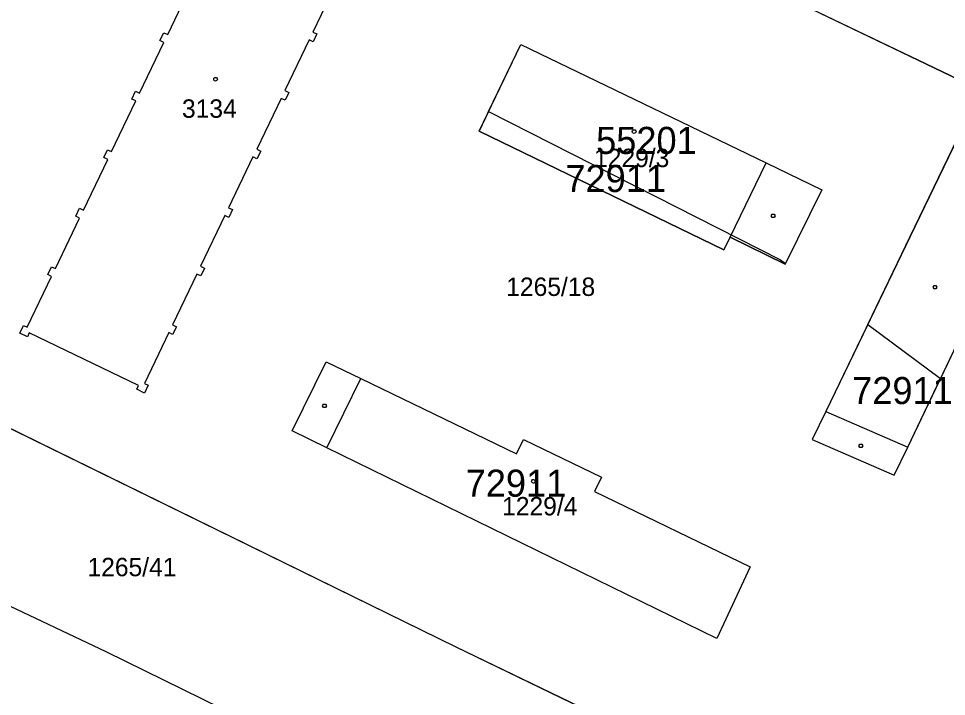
# Model space of a CAD drawing. Extents: x -779618 to -776429, y -1144546 to -1143350.
# Drawn here: x -777222.5 to -777136.8, y -1143980.2 to -1143917.5 of the extents above; entities that cross this region are included whole.
import ezdxf

# ---------------------------------------------------------------- set-up
doc = ezdxf.new("R2010")
doc.units = 0
for name, color, linetype in [('1', 7, 'Continuous'), ('11', 7, 'Continuous'), ('12', 7, 'Continuous'), ('2', 7, 'Continuous'), ('4', 7, 'Continuous'), ('5', 7, 'Continuous')]:
    doc.layers.add(name, color=color, linetype=linetype)

msp = doc.modelspace()

# ---------------------------------------------------------------- linework, layer by layer
at = {"layer": '1'}
for p, q in [((-777133.63, -1143924.16), (-777157.17, -1143912.85)), ((-777208.73, -1143919.02), (-777206.49, -1143914.33)), ((-777193.07, -1143914.09), (-777195.31, -1143918.78)), ((-777209.44, -1143919.56), (-777209.09, -1143918.84)), ((-777209.09, -1143918.84), (-777208.73, -1143919.02)), ((-777195.31, -1143918.78), (-777194.95, -1143918.95)), ((-777194.95, -1143918.95), (-777195.3, -1143919.68)), ((-777211.33, -1143924.42), (-777209.08, -1143919.74)), ((-777209.08, -1143919.74), (-777209.44, -1143919.56)), ((-777195.66, -1143919.5), (-777197.91, -1143924.19)), ((-777195.3, -1143919.68), (-777195.66, -1143919.5)), ((-777179.97, -1143927.94), (-777176.1, -1143919.92)), ((-777176.1, -1143919.92), (-777153.45, -1143930.87)), ((-777212.03, -1143924.97), (-777211.69, -1143924.25)), ((-777211.69, -1143924.25), (-777211.33, -1143924.42)), ((-777197.91, -1143924.19), (-777197.55, -1143924.36)), ((-777133.63, -1143924.16), (-777140.15, -1143937.67)), ((-777213.92, -1143929.83), (-777211.67, -1143925.14)), ((-777211.67, -1143925.14), (-777212.03, -1143924.97)), ((-777198.25, -1143924.91), (-777200.5, -1143929.6)), ((-777197.89, -1143925.08), (-777198.25, -1143924.91)), ((-777197.55, -1143924.36), (-777197.89, -1143925.08)), ((-777157.35, -1143938.91), (-777179.97, -1143927.94)), ((-777214.62, -1143930.38), (-777214.28, -1143929.66)), ((-777214.28, -1143929.66), (-777213.92, -1143929.83)), ((-777200.85, -1143930.32), (-777203.1, -1143935.01)), ((-777200.49, -1143930.49), (-777200.85, -1143930.32)), ((-777200.5, -1143929.6), (-777200.14, -1143929.77)), ((-777200.14, -1143929.77), (-777200.49, -1143930.49)), ((-777216.51, -1143935.24), (-777214.26, -1143930.55)), ((-777214.26, -1143930.55), (-777214.62, -1143930.38)), ((-777153.45, -1143930.87), (-777148.31, -1143933.36)), ((-777148.31, -1143933.36), (-777151.69, -1143940.24)), ((-777217.22, -1143935.78), (-777216.87, -1143935.06)), ((-777216.87, -1143935.06), (-777216.51, -1143935.24)), ((-777203.1, -1143935.01), (-777202.74, -1143935.18)), ((-777202.74, -1143935.18), (-777203.08, -1143935.9)), ((-777219.1, -1143940.64), (-777216.86, -1143935.96)), ((-777216.86, -1143935.96), (-777217.22, -1143935.78)), ((-777203.44, -1143935.73), (-777205.69, -1143940.42)), ((-777203.08, -1143935.9), (-777203.44, -1143935.73)), ((-777156.78, -1143937.74), (-777157.35, -1143938.91)), ((-777151.69, -1143940.24), (-777156.78, -1143937.74)), ((-777140.15, -1143937.67), (-777147.94, -1143953.83)), ((-777219.81, -1143941.19), (-777219.46, -1143940.47)), ((-777219.46, -1143940.47), (-777219.1, -1143940.64)), ((-777205.69, -1143940.42), (-777205.33, -1143940.59)), ((-777205.33, -1143940.59), (-777205.68, -1143941.31)), ((-777221.7, -1143946.05), (-777219.45, -1143941.36)), ((-777219.45, -1143941.36), (-777219.81, -1143941.19)), ((-777206.04, -1143941.14), (-777208.29, -1143945.83)), ((-777205.68, -1143941.31), (-777206.04, -1143941.14)), ((-777140.36, -1143957.12), (-777132.6, -1143940.84)), ((-777222.4, -1143946.6), (-777222.06, -1143945.88)), ((-777221.68, -1143946.94), (-777222.4, -1143946.6)), ((-777222.06, -1143945.88), (-777221.7, -1143946.05)), ((-777221.51, -1143946.58), (-777221.68, -1143946.94)), ((-777211.42, -1143951.42), (-777221.51, -1143946.58)), ((-777208.63, -1143946.55), (-777210.88, -1143951.24)), ((-777208.27, -1143946.72), (-777208.63, -1143946.55)), ((-777208.29, -1143945.83), (-777207.93, -1143946)), ((-777207.93, -1143946), (-777208.27, -1143946.72)), ((-777197.24, -1143955.62), (-777194.08, -1143949.25)), ((-777194.08, -1143949.25), (-777190.89, -1143950.8)), ((-777233.61, -1143950.34), (-777182.11, -1143975.59)), ((-777190.89, -1143950.8), (-777176.5, -1143957.76)), ((-777211.59, -1143951.78), (-777211.42, -1143951.42)), ((-777210.88, -1143951.24), (-777210.52, -1143951.41)), ((-777210.52, -1143951.41), (-777210.87, -1143952.13)), ((-777210.87, -1143952.13), (-777211.59, -1143951.78)), ((-777263.88, -1143952.69), (-777214.44, -1143976.01)), ((-777147.94, -1143953.83), (-777149.2, -1143956.43)), ((-777194.04, -1143957.18), (-777197.24, -1143955.62)), ((-777176.5, -1143957.76), (-777175.86, -1143956.43)), ((-777175.86, -1143956.43), (-777168.67, -1143959.91)), ((-777149.2, -1143956.43), (-777141.61, -1143959.73)), ((-777157.99, -1143974.82), (-777194.04, -1143957.18)), ((-777141.61, -1143959.73), (-777140.36, -1143957.12)), ((-777168.67, -1143959.91), (-777169.31, -1143961.24)), ((-777169.31, -1143961.24), (-777154.93, -1143968.2)), ((-777154.93, -1143968.2), (-777157.99, -1143974.82)), ((-777182.11, -1143975.59), (-777151.49, -1143990.35)), ((-777214.44, -1143976.01), (-777171.18, -1143997.24))]:
    msp.add_line(p, q, dxfattribs=at)
at = {"layer": '11'}
msp.add_line((-777144.07, -1143945.8), (-777137.35, -1143950.8), dxfattribs=at)
for points in [[(-777144.07, -1143945.8), (-777140.15, -1143937.67), (-777133.63, -1143924.16), (-777157.17, -1143912.85), (-777169.76, -1143906.8), (-777164.83, -1143896.6), (-777152.28, -1143902.66), (-777127.18, -1143914.79), (-777125.66, -1143911.89), (-777123.69, -1143912.92), (-777122.34, -1143910.06), (-777116.5, -1143912.8), (-777119.25, -1143918.66), (-777099.16, -1143928.16), (-777100.35, -1143930.67), (-777097.85, -1143931.84), (-777100.33, -1143937.03), (-777102.79, -1143935.87), (-777103.98, -1143938.41), (-777126.31, -1143927.68), (-777132.6, -1143940.84), (-777137.35, -1143950.8)], [(-777179.09, -1143926.12), (-777176.1, -1143919.92), (-777153.45, -1143930.87), (-777148.31, -1143933.36), (-777151.65, -1143940.15)], [(-777179.09, -1143926.12), (-777179.97, -1143927.94), (-777157.35, -1143938.91), (-777156.78, -1143937.74), (-777151.69, -1143940.24), (-777151.65, -1143940.15)], [(-777179.09, -1143926.12), (-777152.11, -1143939.81), (-777151.65, -1143940.15)], [(-777144.07, -1143945.8), (-777147.94, -1143953.83), (-777149.2, -1143956.43), (-777141.61, -1143959.73), (-777140.36, -1143957.12), (-777137.35, -1143950.8)], [(-777233.61, -1143950.34), (-777182.11, -1143975.59), (-777151.49, -1143990.35), (-777149.1, -1143989.23), (-777148.68, -1143990.13), (-777144.83, -1143988.32), (-777141.63, -1143995.11), (-777128.13, -1144001.62), (-777129.93, -1143997.79), (-777127.9, -1143996.84), (-777129.57, -1143993.28), (-777118.21, -1143987.96), (-777116.54, -1143991.53), (-777114.5, -1143990.57), (-777103.79, -1144013.4), (-777099.68, -1144015.4), (-777097.63, -1144016.39), (-777109.29, -1143991.28), (-777109.82, -1143985.95), (-777106.25, -1143978.69)]]:
    msp.add_lwpolyline(points, dxfattribs=at)
msp.add_lwpolyline([(-777194.08, -1143949.25), (-777190.89, -1143950.8), (-777176.5, -1143957.76), (-777175.86, -1143956.43), (-777168.67, -1143959.91), (-777169.31, -1143961.24), (-777154.93, -1143968.2), (-777157.99, -1143974.82), (-777194.04, -1143957.18), (-777197.24, -1143955.62)], close=True, dxfattribs=at)
at = {"layer": '12'}
for p, q in [((-777133.63, -1143924.16), (-777157.17, -1143912.85)), ((-777208.73, -1143919.02), (-777206.49, -1143914.33)), ((-777193.07, -1143914.09), (-777195.31, -1143918.78)), ((-777209.44, -1143919.56), (-777209.09, -1143918.84)), ((-777209.09, -1143918.84), (-777208.73, -1143919.02)), ((-777195.31, -1143918.78), (-777194.95, -1143918.95)), ((-777194.95, -1143918.95), (-777195.3, -1143919.68)), ((-777211.33, -1143924.42), (-777209.08, -1143919.74)), ((-777209.08, -1143919.74), (-777209.44, -1143919.56)), ((-777195.66, -1143919.5), (-777197.91, -1143924.19)), ((-777195.3, -1143919.68), (-777195.66, -1143919.5)), ((-777179.97, -1143927.94), (-777176.1, -1143919.92)), ((-777176.1, -1143919.92), (-777153.45, -1143930.87)), ((-777212.03, -1143924.97), (-777211.69, -1143924.25)), ((-777211.69, -1143924.25), (-777211.33, -1143924.42)), ((-777197.91, -1143924.19), (-777197.55, -1143924.36)), ((-777213.92, -1143929.83), (-777211.67, -1143925.14)), ((-777211.67, -1143925.14), (-777212.03, -1143924.97)), ((-777198.25, -1143924.91), (-777200.5, -1143929.6)), ((-777197.89, -1143925.08), (-777198.25, -1143924.91)), ((-777197.55, -1143924.36), (-777197.89, -1143925.08)), ((-777157.35, -1143938.91), (-777179.97, -1143927.94)), ((-777214.62, -1143930.38), (-777214.28, -1143929.66)), ((-777214.28, -1143929.66), (-777213.92, -1143929.83)), ((-777200.85, -1143930.32), (-777203.1, -1143935.01)), ((-777200.49, -1143930.49), (-777200.85, -1143930.32)), ((-777200.5, -1143929.6), (-777200.14, -1143929.77)), ((-777200.14, -1143929.77), (-777200.49, -1143930.49)), ((-777216.51, -1143935.24), (-777214.26, -1143930.55)), ((-777214.26, -1143930.55), (-777214.62, -1143930.38)), ((-777156.78, -1143937.74), (-777153.45, -1143930.87)), ((-777217.22, -1143935.78), (-777216.87, -1143935.06)), ((-777216.87, -1143935.06), (-777216.51, -1143935.24)), ((-777203.1, -1143935.01), (-777202.74, -1143935.18)), ((-777202.74, -1143935.18), (-777203.08, -1143935.9)), ((-777219.1, -1143940.64), (-777216.86, -1143935.96)), ((-777216.86, -1143935.96), (-777217.22, -1143935.78)), ((-777203.44, -1143935.73), (-777205.69, -1143940.42)), ((-777203.08, -1143935.9), (-777203.44, -1143935.73)), ((-777156.78, -1143937.74), (-777157.35, -1143938.91)), ((-777219.81, -1143941.19), (-777219.46, -1143940.47)), ((-777219.46, -1143940.47), (-777219.1, -1143940.64)), ((-777205.69, -1143940.42), (-777205.33, -1143940.59)), ((-777205.33, -1143940.59), (-777205.68, -1143941.31)), ((-777221.7, -1143946.05), (-777219.45, -1143941.36)), ((-777219.45, -1143941.36), (-777219.81, -1143941.19)), ((-777206.04, -1143941.14), (-777208.29, -1143945.83)), ((-777205.68, -1143941.31), (-777206.04, -1143941.14)), ((-777222.4, -1143946.6), (-777222.06, -1143945.88)), ((-777221.68, -1143946.94), (-777222.4, -1143946.6)), ((-777222.06, -1143945.88), (-777221.7, -1143946.05)), ((-777221.51, -1143946.58), (-777221.68, -1143946.94)), ((-777211.42, -1143951.42), (-777221.51, -1143946.58)), ((-777208.63, -1143946.55), (-777210.88, -1143951.24)), ((-777208.27, -1143946.72), (-777208.63, -1143946.55)), ((-777208.29, -1143945.83), (-777207.93, -1143946)), ((-777207.93, -1143946), (-777208.27, -1143946.72)), ((-777194.04, -1143957.18), (-777190.89, -1143950.8)), ((-777190.89, -1143950.8), (-777176.5, -1143957.76)), ((-777211.59, -1143951.78), (-777211.42, -1143951.42)), ((-777210.88, -1143951.24), (-777210.52, -1143951.41)), ((-777210.52, -1143951.41), (-777210.87, -1143952.13)), ((-777210.87, -1143952.13), (-777211.59, -1143951.78)), ((-777176.5, -1143957.76), (-777175.86, -1143956.43)), ((-777175.86, -1143956.43), (-777168.67, -1143959.91)), ((-777157.99, -1143974.82), (-777194.04, -1143957.18)), ((-777168.67, -1143959.91), (-777169.31, -1143961.24)), ((-777169.31, -1143961.24), (-777154.93, -1143968.2)), ((-777154.93, -1143968.2), (-777157.99, -1143974.82))]:
    msp.add_line(p, q, dxfattribs=at)
at = {"layer": '4'}
for p, q in [((-777156.78, -1143937.74), (-777153.45, -1143930.87)), ((-777194.04, -1143957.18), (-777190.89, -1143950.8)), ((-777147.94, -1143953.83), (-777140.36, -1143957.12))]:
    msp.add_line(p, q, dxfattribs=at)
at = {"layer": '5'}
for points in [[(-777204.31, -1143922.97), (-777204.21, -1143922.99), (-777204.16, -1143923.08), (-777204.14, -1143923.14), (-777204.16, -1143923.23), (-777204.24, -1143923.3), (-777204.31, -1143923.31), (-777204.4, -1143923.28), (-777204.46, -1143923.22), (-777204.48, -1143923.14), (-777204.46, -1143923.05), (-777204.38, -1143922.98)], [(-777165.64, -1143927.8), (-777165.54, -1143927.82), (-777165.49, -1143927.91), (-777165.47, -1143927.97), (-777165.49, -1143928.06), (-777165.57, -1143928.13), (-777165.64, -1143928.14), (-777165.73, -1143928.11), (-777165.79, -1143928.05), (-777165.81, -1143927.97), (-777165.79, -1143927.88), (-777165.71, -1143927.81)], [(-777152.72, -1143935.61), (-777152.63, -1143935.76), (-777152.72, -1143935.91), (-777152.9, -1143935.91), (-777152.99, -1143935.76), (-777152.9, -1143935.61)], [(-777137.76, -1143942.2), (-777137.67, -1143942.35), (-777137.76, -1143942.5), (-777137.94, -1143942.5), (-777138.03, -1143942.35), (-777137.94, -1143942.2)], [(-777194.16, -1143953.16), (-777194.07, -1143953.31), (-777194.16, -1143953.46), (-777194.34, -1143953.46), (-777194.43, -1143953.31), (-777194.34, -1143953.16)], [(-777144.61, -1143956.85), (-777144.52, -1143957), (-777144.61, -1143957.15), (-777144.79, -1143957.15), (-777144.88, -1143957), (-777144.79, -1143956.85)], [(-777174.95, -1143960.12), (-777174.85, -1143960.14), (-777174.8, -1143960.23), (-777174.78, -1143960.29), (-777174.8, -1143960.38), (-777174.88, -1143960.45), (-777174.95, -1143960.46), (-777175.04, -1143960.43), (-777175.1, -1143960.37), (-777175.12, -1143960.29), (-777175.1, -1143960.2), (-777175.02, -1143960.13)]]:
    msp.add_lwpolyline(points, close=True, dxfattribs=at)

# ---------------------------------------------------------------- texts
at = {"layer": '11'}
for s, p in [('55201', (-777169.155, -1143930.04)), ('72911', (-777171.995, -1143933.56)), ('72911', (-777145.505, -1143953.15)), ('72911', (-777181.205, -1143961.71))]:
    msp.add_text(s, height=2.5, dxfattribs=at).set_placement(p)
at = {"layer": '2'}
for s, p in [('3134', (-777207.409, -1143926.7)), ('1229/3', (-777169.347, -1143931.26)), ('1265/18', (-777177.457, -1143943.16)), ('1229/4', (-777177.837, -1143963.44)), ('1265/41', (-777216.137, -1143969.06))]:
    msp.add_text(s, height=1.7, dxfattribs=at).set_placement(p)

doc.saveas('drawing.dxf')
